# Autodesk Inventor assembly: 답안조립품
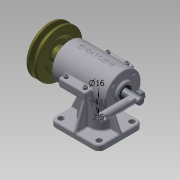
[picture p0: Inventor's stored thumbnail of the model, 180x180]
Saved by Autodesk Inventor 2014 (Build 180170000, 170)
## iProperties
Created: 2015-05
Part Number: 답안조립품
Document SubType Name: Assembly
Designer: Administrator
Mass: 1941.79 g
Surface Area: 1472.73 cm^2
Volume: 476.402 cm^3
Density: 4.07595 g/cm^3
Author: Administrator
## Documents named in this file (18)
- C:\Documents and Settings\Administrator\바탕 화면\350508V1012\답안조립품.iam
- C:\Documents and Settings\Administrator\바탕 화면\350508V1012\스프링.ipt
- C:\Documents and Settings\Administrator\바탕 화면\350508V1012\본체.ipt
- C:\Documents and Settings\Administrator\바탕 화면\350508V1012\본체 커버.ipt
- C:\Documents and Settings\Administrator\바탕 화면\350508V1012\M4x0.5x14.ipt
- C:\Documents and Settings\Administrator\바탕 화면\350508V1012\앞커버.ipt
- C:\Documents and Settings\Administrator\바탕 화면\350508V1012\뒤커버.ipt
- C:\Documents and Settings\Administrator\바탕 화면\350508V1012\M3x0.5x8.ipt
- C:\Documents and Settings\Administrator\바탕 화면\350508V1012\편심축.ipt
- C:\Documents and Settings\Administrator\바탕 화면\350508V1012\베어링 6201.ipt
- C:\Documents and Settings\Administrator\바탕 화면\350508V1012\베어링 6202.ipt
- C:\Documents and Settings\Administrator\바탕 화면\350508V1012\오일실.ipt
- C:\Documents and Settings\Administrator\바탕 화면\350508V1012\키4x4.ipt
- C:\Documents and Settings\Administrator\바탕 화면\350508V1012\V-벨트풀리.ipt
- C:\Documents and Settings\Administrator\바탕 화면\350508V1012\멈춤나사.ipt
- C:\Documents and Settings\Administrator\바탕 화면\350508V1012\링크.ipt
- C:\Documents and Settings\Administrator\바탕 화면\350508V1012\너트 M8.ipt
- C:\Documents and Settings\Administrator\바탕 화면\350508V1012\슬라이드.ipt
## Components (14 placed, 4 different names)
1. M4x0.5x14:1
2. M4x0.5x14:2
3. M4x0.5x14:3
4. M4x0.5x14:4
5. V-벨트풀리:1 — 플러쉬:1, 구동부
6. KS B 1012 C - 미터 C M8:1
7. M3x0.5x8:1
8. M3x0.5x8:3
9. M3x0.5x8:4
10. M3x0.5x8:5
11. M3x0.5x8:2
12. M3x0.5x8:6
13. M3x0.5x8:7
14. M3x0.5x8:8
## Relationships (2: Flush 1, Angle 1)
- 플러쉬:1 [Flush]: V-벨트풀리:1
- 구동부 [Angle]: V-벨트풀리:1
